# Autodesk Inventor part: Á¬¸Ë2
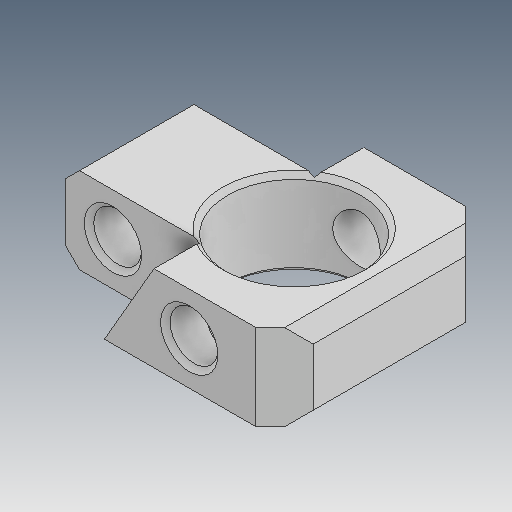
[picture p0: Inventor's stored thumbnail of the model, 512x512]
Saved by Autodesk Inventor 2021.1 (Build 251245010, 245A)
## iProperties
Created: 2015-08
Part Number: Á¬¸Ë2
Material: Ogólny
Document SubType Name: Modeling
Designer: user
Density: 1 g/cm^3
Appearance: Domyślna
Author: user
Revision Number: ÈÎºÎ
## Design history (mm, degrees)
feature "µ¹½Ç2"
node "Bryła1"
